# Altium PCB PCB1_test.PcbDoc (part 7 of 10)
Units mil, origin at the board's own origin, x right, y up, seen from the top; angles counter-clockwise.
Board outline 6690 x 6690 mil, 6 copper layers (Layer 1 - Top Layer, Layer 2 - GND, Layer 3 - PWR, Layer 4 - Signal, Layer 5 - GND, Layer 6 - Bottom Layer), stack 80.244 mil thick; 821 components, 458 nets, 3752 pads, 1525 vias.
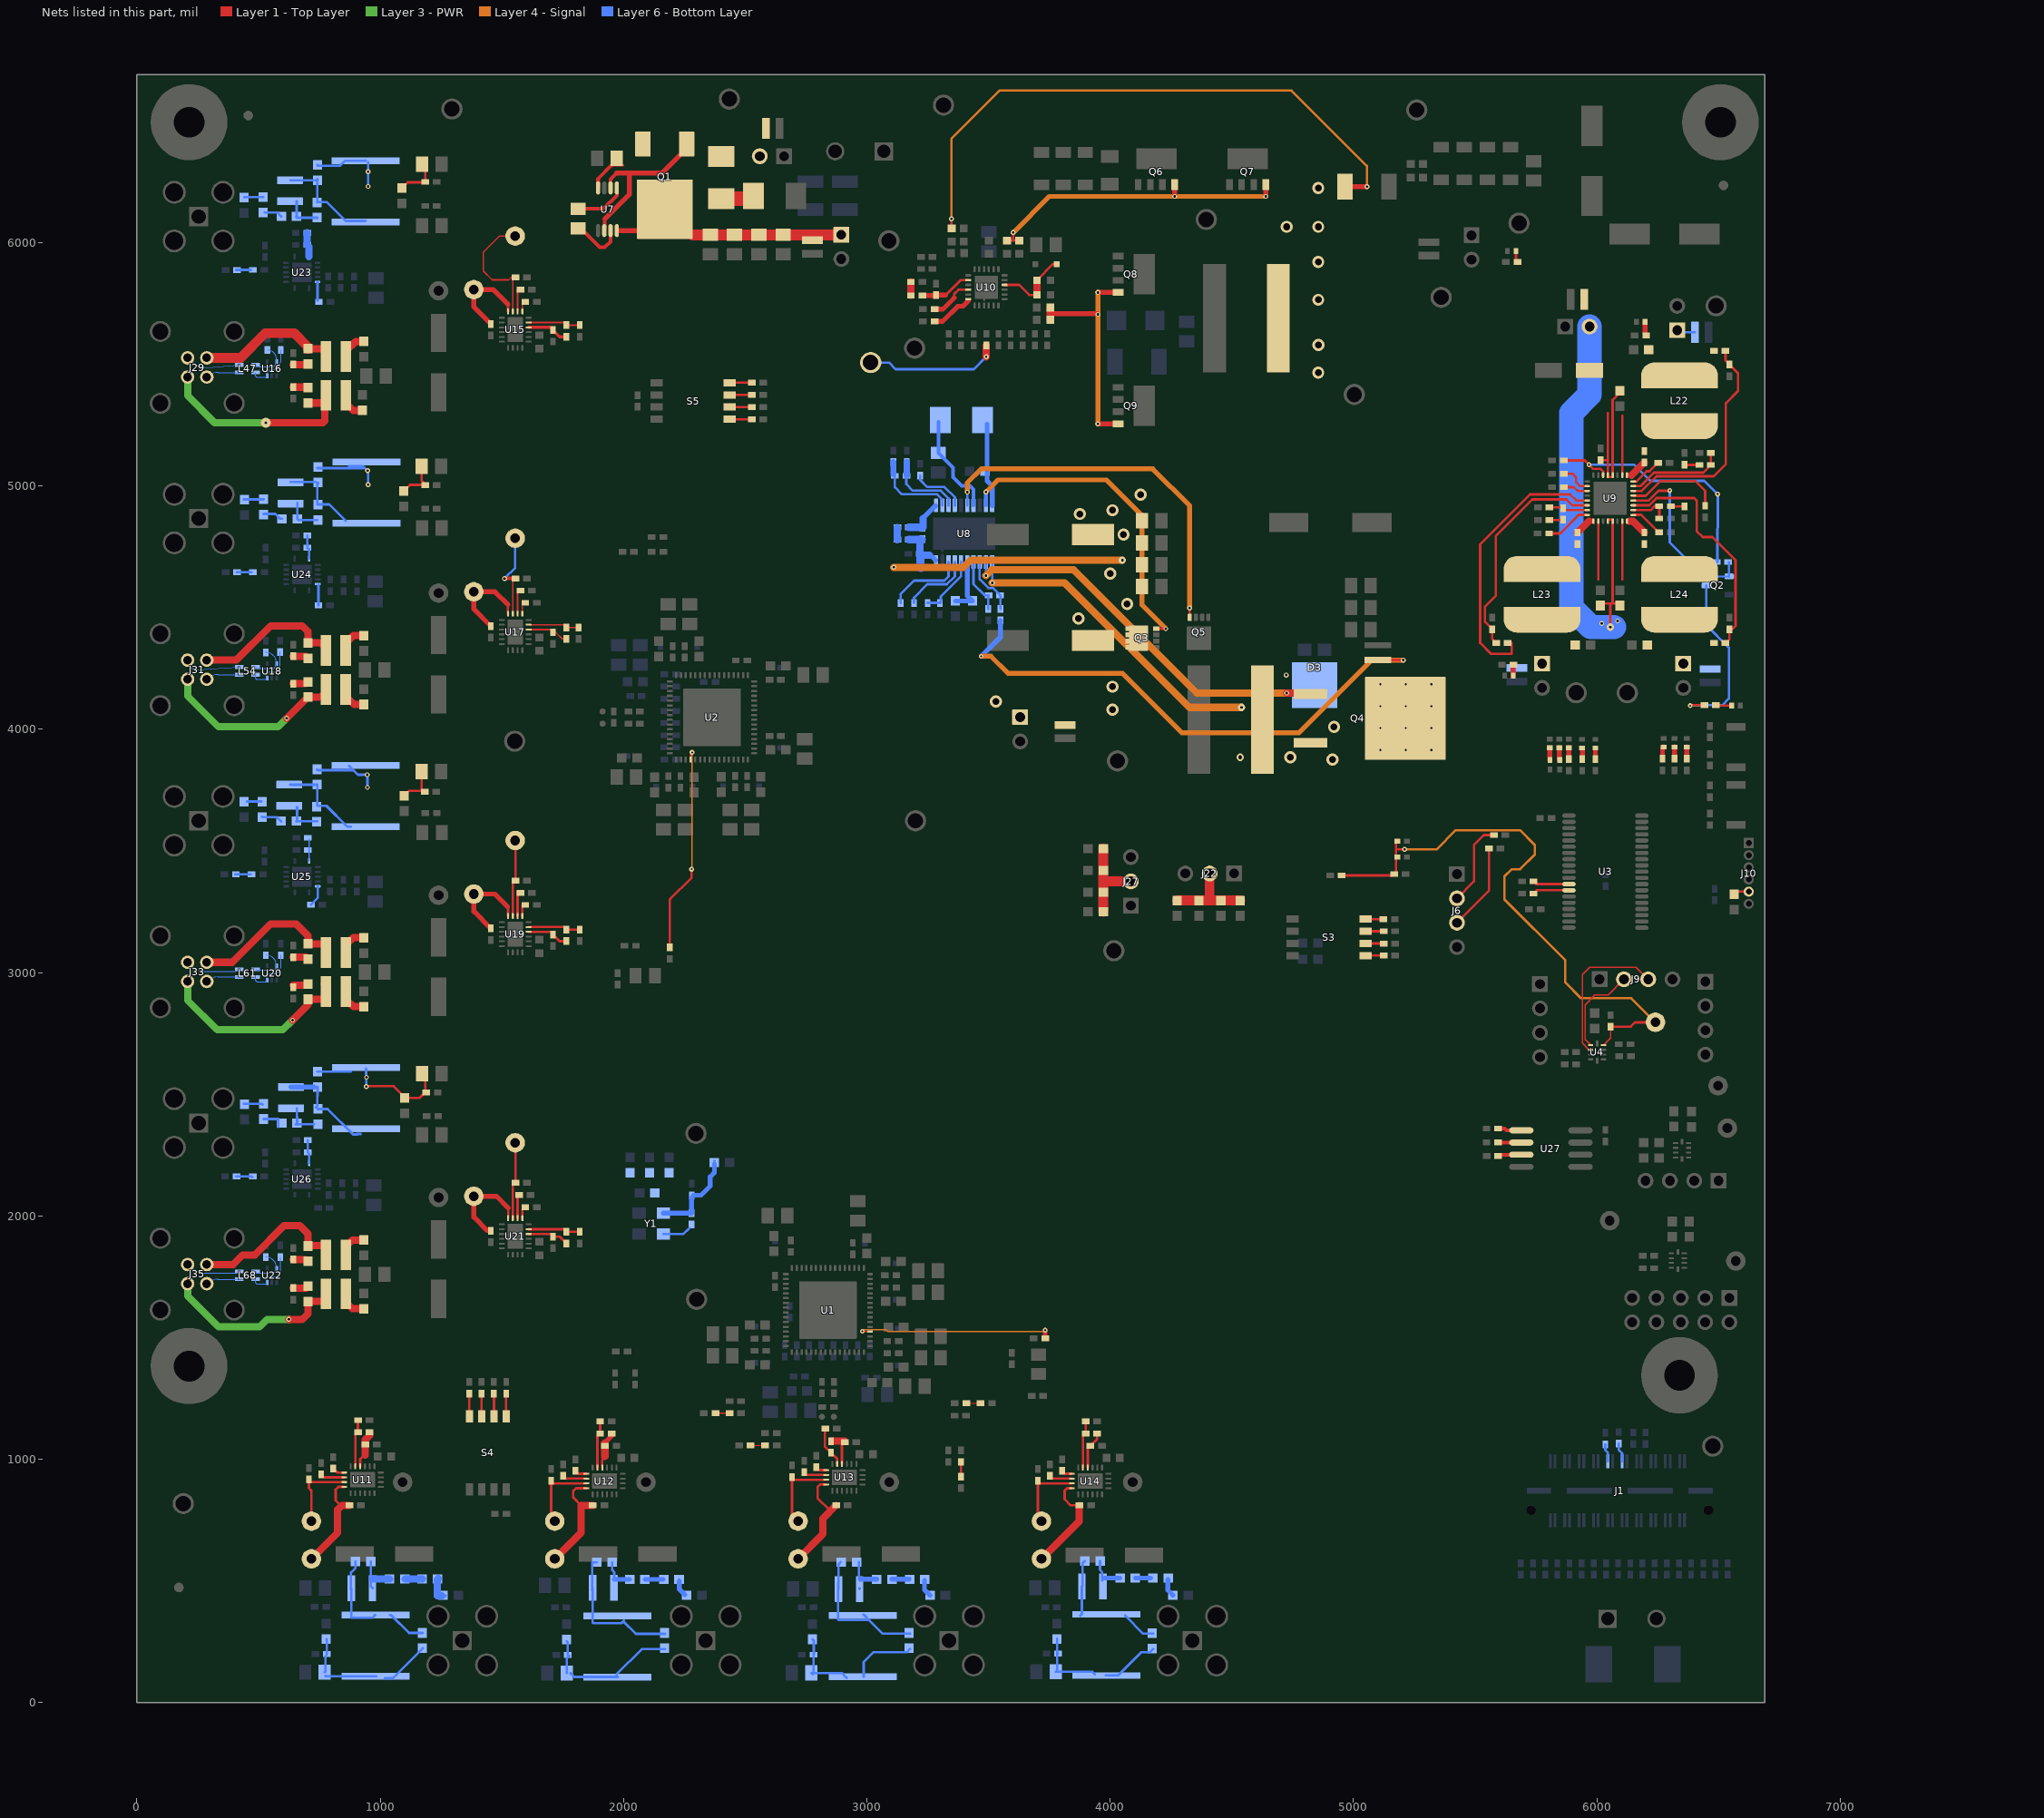
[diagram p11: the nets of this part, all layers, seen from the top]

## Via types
v1: diameter 20, hole 10, Layer 1 - Top Layer to Layer 6 - Bottom Layer, tented both sides, 491 vias
v2: diameter 20, hole 10, Layer 1 - Top Layer to Layer 6 - Bottom Layer, 310 vias
v3: diameter 19.68, hole 7.87, Layer 1 - Top Layer to Layer 6 - Bottom Layer, 274 vias
v4: diameter 19.68, hole 7.87, Layer 1 - Top Layer to Layer 6 - Bottom Layer, tented both sides, 217 vias
v5: diameter 50, hole 28, Layer 1 - Top Layer to Layer 6 - Bottom Layer, 101 vias
v6: diameter 30, hole 15, Layer 1 - Top Layer to Layer 6 - Bottom Layer, 73 vias
v7: diameter 22, hole 10, Layer 1 - Top Layer to Layer 6 - Bottom Layer, 36 vias
v8: diameter 30, hole 10, Layer 1 - Top Layer to Layer 6 - Bottom Layer, 14 vias
v9: diameter 19.68, hole 7.87, Layer 1 - Top Layer to Layer 6 - Bottom Layer, tented bottom, 4 vias
v10: diameter 30, hole 10, Layer 1 - Top Layer to Layer 6 - Bottom Layer, tented both sides, 2 vias
v11: diameter 40, hole 10, Layer 1 - Top Layer to Layer 6 - Bottom Layer, 1 vias
v12: diameter 23.62, hole 7.87, Layer 1 - Top Layer to Layer 6 - Bottom Layer, tented both sides, 1 vias
v13: diameter 23.62, hole 7.87, Layer 1 - Top Layer to Layer 6 - Bottom Layer, 1 vias

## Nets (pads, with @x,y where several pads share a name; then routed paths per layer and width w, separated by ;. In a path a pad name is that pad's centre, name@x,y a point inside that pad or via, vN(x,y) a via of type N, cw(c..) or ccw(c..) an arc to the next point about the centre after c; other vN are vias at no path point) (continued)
NetC132_1: C132.1 D1.1 J12.2 Q1.3 R173.2 U7.4 | length 197.8
  Layer 1 - Top Layer w10: C132.1@1951.2,6317.62 1997.89,6317.62
  Layer 1 - Top Layer w15: U7.4@1895.65,6224.71 1895.65,6262.07 C132.1@1951.2,6317.62 ; Q1.3@2070.76,6374.7 Q1.3@2095.67,6399.61
NetC133_1: C133.1 C134.1 C135.1 C136.1 J13.1 Q1.4 R172.1 U7.8 | length 689.6
  Layer 1 - Top Layer w10: Q1.4@2055.8,6049.51 Q1.4@2056.22,6049.92 ; Q1.4@2067.37,6089.94 Q1.4@2068.5,6091.06
  Layer 1 - Top Layer w20: U7.8@1978.82,6049.51 Q1.4@2055.8,6049.51
  Layer 1 - Top Layer w45: 2284.65,6032.05 C134.1@2357.5,6032.05 C135.1@2456.02,6032.05 C133.1@2656.02,6032.05 2770.71,6032.18 2775.97,6032.19 2783.97,6032.2 J13.1@2895.12,6032.32
NetC137_1: C137.1 U7.7 | length 197
  Layer 1 - Top Layer w15: C137.1@1832,6051.06 1902.38,5980.67 1923.53,5980.67 1946.56,6003.7 U7.7@1946.56,6047.43
NetC137_2: C137.2 U7.1 | length 217.8
  Layer 1 - Top Layer w15: C137.2@1808.17,6138.95 1917.46,6138.95 1972.42,6193.91 U7.1@1972.42,6224.71
NetC142_1: C142.1 C143.1 C144.1 C145.1 C146.1 C147.1 J16.1 Q3.5 Q3.6 Q3.7 Q3.8 Q3.9 R77.2 R187.1 | length 1010.6
  Layer 4 - Signal w30: v4(3110.86,4665.86) 3397.05,4665.86 3426.19,4695 v8(4050,4695)
  Layer 6 - Bottom Layer w20: v4(3110.86,4665.86) R77.2@3170.22,4665.86
  other v5: 4010,4080 3530,4115 4010,4175 3870,4455 4070,4515 4000,4640 4055,4800 3875,4885 4010,4900 4125,4965
NetC148_1: C148.1 R75.1 U8.5 | length 239.1
  Layer 6 - Bottom Layer w20: C148.1@3363.84,4527.35 R75.1@3433.84,4527.35 3412.64,4548.56 U8.5@3412.64,4687.72
NetC149_1: C149.1 R74.1 U8.3 | length 237.4
  Layer 6 - Bottom Layer w10: U8.3@3463.82,4687.72 3463.82,4615.88 3498.84,4580.86 3517.46,4580.86 C149.1@3547.46,4550.86 ; R74.1@3548.84,4494.48 C149.1@3548.84,4549.48
NetC149_2: C149.2 R73.1 U8.4 | length 227.1
  Layer 6 - Bottom Layer w10: U8.4@3438.23,4687.72 3438.23,4596.47 3483.84,4550.86 C149.2@3500.22,4550.86 ; R73.1@3498.84,4494.48 C149.2@3498.84,4549.48
NetC150_1: C150.1 U8.7 | length 284.5
  Layer 6 - Bottom Layer w10: C150.1@3193.84,4519.48 3193.84,4540.86 3248.84,4595.86 3328.84,4595.86 3361.46,4628.47 U8.7@3361.46,4687.72
NetC151_1: C151.1 U8.14 | length 223.1
  Layer 6 - Bottom Layer w10: C151.1@3218.84,5043.06 3218.84,5025.86 3248.84,4995.86 3318.84,4995.86 3361.46,4953.24 U8.14@3361.46,4920
NetC152_1: C152.1 D4.2 U8.17 | length 423.2
  Layer 6 - Bottom Layer w15: D4.2@3293.84,5262.87 C152.1@3293.84,5135.31 3353.84,5075.31 3353.84,5035.86 3388.84,5000.86 3423.84,5000.86 3438.23,4986.47 U8.17@3438.23,4920
NetC153_1: C153.1 C154.1 R77.1 R82.2 U8.10 | length 284.6
  Layer 6 - Bottom Layer w20: 3257.4,4720 U8.10@3283,4694
  Layer 6 - Bottom Layer w30: C154.1@3172.46,4779.66 C153.1@3227.46,4779.66 ; R77.1@3217.46,4665.86 R82.2@3217.46,4720.86 C153.1@3217.46,4768.54 ; R77.1@3221.09,4660.86 3221.09,4715.86 3256.54,4715.86
NetC153_2: C153.2 R84.1 U8.11 | length 170.2
  Layer 6 - Bottom Layer w20: 3227.86,4863.86 U8.11@3282,4918
  Layer 6 - Bottom Layer w30: R84.1@3172.79,4829.98 3230.54,4829.98 3230.54,4865.86
NetC154_2: C154.2 R84.2 | length 50
  Layer 6 - Bottom Layer w30: C154.2@3125.22,4779.66 R84.2@3125.22,4829.66
NetC155_1: C155.1 U9.25 | length 86.5
  Layer 1 - Top Layer w20: 6130,5045 6143.11,5044.49
  Layer 1 - Top Layer w30: 6143.11,5044.49 C155.1@6195,5096.38
NetC155_2: C155.2 L22.1 U9.26 | length 244.7
  Layer 1 - Top Layer w10: U9.26@6104.21,5044.49 6104.21,5289.21
NetC156_1: C156.1 J18.1 L22.2 R85.2 R201.1 | length 76.3
  Layer 6 - Bottom Layer w10: J18.1@6330,5640 6338,5632 R201.1@6403,5632
NetC157_2: C157.2 R86.2 | length 59.8
  Layer 1 - Top Layer w10: C157.2@6361.38,5086.38 R86.2@6421.15,5086.38
NetC158_1: C158.1 C_PVIN1.1 C_PVIN2.1 C_PVIN3.1 C_VIN1.1 J17.2 R200.2 U9.12 U9.13 U9.28 U9.29 | length 2594.1
  Layer 1 - Top Layer w10: C_PVIN2.1@6015,4516.38 6055,4516.38 ; C_VIN1.1@6015,5106.38 6043.78,5106.38 ; U9.12@6045,4862 U9.13@6064.68,4862 ; U9.29@6045,5037 U9.29@6045.16,5037 ; U9.29@6045.16,5036.74 U9.29@6045.16,5037 ; 6045.16,5299.84 U9.29@6045.16,5044.49 U9.29@6045.16,5037 ; v10(6055,4420) 6055,4516.38 ; 6064.84,4516.54 U9.13@6064.84,4855.51 ; U9.28@6064.84,5044.49 6064.84,5353.46 6095,5383.62 C_PVIN1.1@6095,5385 ; U9.28@6065,5037 U9.29@6045.16,5037 ; C_PVIN3.1@6095,4516.38 6055,4516.38
  Layer 6 - Bottom Layer w100: J17.2@5970,5655 5970,5375 5895,5300 5895,4500 5975,4420 v10(6055,4420) 6070,4420
  other v1: 6020,4435 6085,4445
NetC159_2: C159.2 R86.1 U9.23 | length 404.8
  Layer 1 - Top Layer w10: U9.23@6149.49,4999.21 6179.21,4999.21 6235,5055 6437.02,5055 R86.1@6468.4,5086.38 C159.2@6468.4,5136.15
NetC160_1: C160.1 U9.9 | length 78.9
  Layer 1 - Top Layer w20: 5966.89,4855.51 5979.51,4855.51
  Layer 1 - Top Layer w30: C160.1@5920,4808.62 5966.89,4855.51
NetC160_2: C160.2 L23.1 U9.10 | length 239.7
  Layer 1 - Top Layer w10: 6005.79,4615.79 U9.10@6005.79,4855.51
NetC161_1: C161.1 J19.1 L23.2 R91.2 R214.1 U9.5 | length 1150.7
  Layer 1 - Top Layer w10: R91.2@5633.62,4355 5650,4355 5650,4310 5565,4310 5520,4355 5520,4760 5725,4965 5890,4965 5914.84,4940.16 U9.5@5960.51,4940.16
NetC162_2: C162.2 R94.2 | length 55
  Layer 1 - Top Layer w10: C162.2@5804.84,4860 R94.2@5859.84,4860
NetC163_2: C163.2 R94.1 U9.7 | length 144.6
  Layer 1 - Top Layer w10: C163.2@5804.64,4912.04 R94.1@5857.8,4912.04 ; R94.1@5869.05,4900.79 U9.7@5960.51,4900.79
NetC164_1: C164.1 U9.16 | length 81.4
  Layer 1 - Top Layer w30: 6133,4855 6148.11,4855.51 C164.1@6195,4808.62
NetC164_2: C164.2 L24.1 U9.15 | length 239.7
  Layer 1 - Top Layer w10: 6104.21,4615.79 U9.15@6104.21,4855.51
NetC165_1: C165.1 J20.1 L24.2 R97.2 R215.1
NetC166_2: C166.2 R98.2 | length 55
  Layer 1 - Top Layer w10: R98.2@6305,4915.28 C166.2@6360,4915.28
NetC167_1: C167.1 R89.2 U9.30 | length 1053.5
  Layer 1 - Top Layer w10: C167.1@5863.62,5105 5950,5105 v4(5967.5,5087.5) 5985,5070 6015,5070 6025.47,5059.53 U9.30@6025.47,5044.49
  Layer 6 - Bottom Layer w10: v4(5967.5,5087.5) 6152.5,5087.5 6218.83,5021.17 6440.84,5021.17 6497.14,4964.88 R89.2@6495.51,4687.57
  other v4: 6496,4966.58
NetC168_1: C168.1 U9.24 | length 133.4
  Layer 1 - Top Layer w10: U9.24@6149.49,5018.9 6163.9,5018.9 6205,5060 6216.38,5060 C168.1@6251.38,5095
NetC169_1: C169.1 U9.8 | length 188.4
  Layer 1 - Top Layer w10: C169.1@5803.62,4805 5849.72,4805 5925.82,4881.1 U9.8@5960.51,4881.1
NetC170_1: C170.1 U9.17 | length 136.3
  Layer 1 - Top Layer w10: U9.17@6149.49,4881.1 6181.34,4881.1 6252.44,4810 C170.1@6256.38,4810
NetC171_2: C171.2 R98.1 U9.18 | length 163.5
  Layer 1 - Top Layer w10: U9.18@6149.49,4900.79 6220.79,4900.79 6236.65,4916.65 R98.1@6256.38,4916.65 C171.2@6256.38,4866.65
NetC180_1: C180.1 C181.2 D9.2 U10.10 | length 318.1
  Layer 1 - Top Layer w10: U10.10@3566.18,5826.22 3626.54,5826.22 3667.76,5785 C181.2@3698.38,5785 ; C180.1@3698.38,5845 3764.76,5911.38 D9.2@3779.69,5911.38
  Layer 1 - Top Layer w30: C181.2@3698.38,5785 C180.1@3698.38,5845
NetC192_1: C192.1 U10.22 | length 181
  Layer 1 - Top Layer w10: 3359,5773 3359,5789 3376.54,5806.54 U10.22@3416.57,5806.54
  Layer 1 - Top Layer w20: C192.1@3278.19,5726.38 3312.38,5726.38 3359,5773
NetC193_1: C193.1 U10.24 | length 172.8
  Layer 1 - Top Layer w20: C193.1@3278.19,5676.38 3311.38,5676.38 3374,5739 3396,5739 3416.57,5759.57
NetC194_2: C194.2 R123.2 U10.20 | length 212.5
  Layer 1 - Top Layer w10: 3324.41,5784.41 3385.91,5845.91 U10.20@3416.57,5845.91
  Layer 1 - Top Layer w20: R123.2@3228.19,5783.03 C194.2@3283.19,5783.03 ; C194.2@3284.57,5784.41 3324.41,5784.41
NetC195_1: C195.1 R123.1 | length 55
  Layer 1 - Top Layer w30: R123.1@3180.94,5783.03 C195.1@3180.94,5838.03
NetC196_1: C196.1 C197.1 L26.1 L79.2 R134.2 | length 543.3
  Layer 6 - Bottom Layer w10: C197.1@772.27,125.13 775,127.86 C196.1@775,190 ; C197.1@775,110 776.89,108.11 L79.2@984.13,108.11 ; L26.1@780,260 780.9,259.1 C196.1@780.9,199.13 ; L79.2@1020,100 1051.5,100 R134.2@1175,223.5
NetC200_1: C200.1 C201.1 L27.1 L80.2 R135.2 | length 580.1
  Layer 6 - Bottom Layer w10: C201.1@1766.93,121.41 1766.93,181.41 C200.1@1776.93,191.41 ; L27.1@1766.93,251.41 1770.56,247.79 C200.1@1770.56,196.41 ; C201.1@1781.93,121.41 1797.92,105.43 L80.2@1976.93,105.43 ; L80.2@1971.93,111.41 1971.93,116.41 2075.44,219.91 R135.2@2171.93,219.91
NetC206_1: C206.1 R132.2 | length 55.6
  Layer 1 - Top Layer w5: R132.2@2383.41,1190 C206.1@2436.38,1190
  Layer 1 - Top Layer w10: R132.2@2381,1189 cw(c2383.41,1186.59) R132.2@2383.41,1190
NetC207_1: C207.1 R133.2 | length 66
  Layer 1 - Top Layer w3.94: R133.2@2522.62,1057 C207.1@2582.38,1057
  Layer 1 - Top Layer w10: R133.2@2518,1053 2522,1057 R133.2@2522.62,1057
NetC214_1: C214.1 U11.18 | length 100
  Layer 1 - Top Layer w5: C214.1@757.56,937.24 C214.1@769.09,925.71
  Layer 1 - Top Layer w10: C214.1@769.09,925.71 U11.18@852.75,925.71
NetC215_1: C215.1 U12.18 | length 83.7
  Layer 1 - Top Layer w10: C215.1@1764.09,920.71 U12.18@1847.75,920.71
NetC216_1: C216.1 C217.1 L34.1 L81.2 R154.2 | length 572.5
  Layer 6 - Bottom Layer w10: C217.1@2771.93,121.92 C217.1@2780.56,121.92 ; C217.1@2776.93,116.92 2780.56,120.54 C217.1@2780.56,121.92 ; L34.1@2776.93,260.43 2781.93,255.42 C216.1@2781.93,196.92 ; C216.1@2780.56,196.92 C217.1@2780.56,121.92 ; L81.2@2916.93,101.92 2896.93,121.92 C217.1@2780.56,121.92 ; L81.2@2986.93,106.92 2986.93,166.92 3026.93,206.92 3163.43,206.92 R154.2@3176.93,220.43
NetC220_1: C220.1 C221.1 L35.1 L82.2 R155.2 | length 535.6
  Layer 6 - Bottom Layer w10: C221.1@3776.93,126.92 3926.93,126.92 L82.2@3936.93,116.92 ; C221.1@3781.93,131.92 3781.93,198.3 C220.1@3785.56,201.92 ; C220.1@3781.93,201.92 L35.1@3781.93,261.92 ; L82.2@3981.93,111.92 4031.93,111.92 4126.93,206.92 4163.43,206.92 R155.2@4176.93,220.43
NetC226_1: C226.1 R152.2 | length 68.4
  Layer 1 - Top Layer w10: C226.1@3386.56,989.24 3386.56,922.07 ccw(c3388.07,922.07) R152.2@3387,921
NetC227_1: C227.1 R153.2 | length 56.6
  Layer 1 - Top Layer w3.94: C227.1@3408.62,1230 R153.2@3462.59,1230
  Layer 1 - Top Layer w10: R153.2@3462.59,1230 ccw(c3462.59,1233.41) R153.2@3465,1231
NetC234_1: C234.1 U13.18 | length 78.7
  Layer 1 - Top Layer w10: C234.1@2754.09,935.71 U13.18@2832.75,935.71
NetC235_1: C235.1 U14.18 | length 78.7
  Layer 1 - Top Layer w10: C235.1@3764.09,920.71 U14.18@3842.75,920.71
NetC236_1: C236.1 C237.1 L42.1 L83.2 R185.2 | length 495.5
  Layer 1 - Top Layer w10: L42.1@1089,6224 1113,6248 1180.5,6248 1185,6252.5 1185,6309.5 C237.1@1172,6322.5
  Layer 6 - Bottom Layer w10: R185.2@742.28,6320.02 R185.2@746.28,6316.02 ; R185.2@744,6316 835,6316 855.02,6336.02 L83.2@940.28,6336.02 940.28,6336.72 L83.2@940,6337 ; v2@950,6228 v2(950,6231) v2@950,6289 ; v2(950,6291) L83.2@950,6331
NetC241_1: C241.1 L47.3 U16.3 | length 209
  Layer 6 - Bottom Layer w3.94: L47.3@488.46,5466.25 488.46,5452.54 ccw(c494,5452.54) 494,5447 529.84,5447 ccw(c529.84,5452.47) U16.3@535.32,5452.47 535.31,5466.31 cw(c544,5466.31) 544,5475 548.59,5475 ccw(c548.59,5520) 593.59,5520 593.59,5556.6 ccw(c591.81,5556.6) C241.1@591.81,5558.38
NetC244_1: C244.1 L47.2 U16.5 | length 169
  Layer 6 - Bottom Layer w3.94: L47.2@488.46,5497.75 ccw(c507.17,5516.45) 507.17,5490 553.16,5490 ccw(c553.16,5511.53) U16.5@574.69,5511.53 574.69,5520.5 ccw(c536.81,5520.5) C244.1@536.81,5558.38
NetC246_1: C246.1 U15.18 | length 90.4
  Layer 1 - Top Layer w6: U15.18@1564.84,5716.8 C246.1@1564.84,5807.16
NetC247_1: C247.1 J29.3 L45.1 | length 856.7
  Layer 1 - Top Layer w30: v11(530,5260) 765,5260 ; C247.1@703,5340.88 L45.1@772.5,5340.88 ; 770,5265 772.92,5267.92 L45.1@772.92,5372.38
  Layer 3 - PWR w30: J29.3@208.94,5447.63 208.94,5371.06 320,5260 v11(530,5260)
NetC247_2: C247.2 R182.2 | length 57.9
  Layer 1 - Top Layer w30: R182.2@643,5406 C247.2@700.87,5406
NetC248_1: C248.1 J29.1 L46.1 | length 588.3
  Layer 1 - Top Layer w10: L46.1@769.5,5563.87 772.92,5560.46 L46.1@772.92,5532.38
  Layer 1 - Top Layer w30: C248.1@703,5563.87 L46.1@769.5,5563.87
  Layer 1 - Top Layer w40: J29.1@287.68,5526.37 426.37,5526.37 527.87,5627.87 647.49,5627.87 703,5572.37 C248.1@703,5563.87
NetC248_2: C248.2 R183.2 | length 57.9
  Layer 1 - Top Layer w30: R183.2@643,5498.76 C248.2@700.87,5498.76
NetC249_1: C249.1 R184.2 | length 61.4
  Layer 6 - Bottom Layer w10: R184.2@407.62,5888 C249.1@469,5888
NetC251_1: C251.1 C252.1 L49.1 L84.2 R199.2 | length 512.2
  Layer 1 - Top Layer w10: L49.1@1097,4979 1122.5,5004.5 C251.1@1183,5004.5 ; C252.1@1171,5080.5 1171,5021.5 C251.1@1189,5003.5
  Layer 6 - Bottom Layer w10: R199.2@742,5073.47 927.3,5073.47 ccw(c927.3,5095.67) 935.11,5074.89 ; 872,5081 929,5081 935.11,5074.89 ; v2@948,5062 935.11,5074.89 ; v2(951,5005) v2@951,5059
  other v2: 949,5063
NetC256_1: C256.1 L54.3 U18.3 | length 210.3
  Layer 6 - Bottom Layer w3.94: L54.3@488.46,4224.25 488.46,4210.54 ccw(c494,4210.54) 494,4205 529.84,4205 ccw(c529.84,4210.47) U18.3@535.32,4210.47 535.31,4224.31 cw(c546,4224.31) 546,4235 559.84,4235 ccw(c559.84,4264.16) 589,4264.16 C256.1@589,4317.38
NetC259_1: C259.1 L54.2 U18.5 | length 171.3
  Layer 6 - Bottom Layer w3.94: L54.2@488.46,4255.75 ccw(c502.34,4269.62) 502.34,4250 555.16,4250 ccw(c555.16,4269.53) U18.5@574.69,4269.53 574.69,4271.69 ccw(c530,4271.69) C259.1@530,4316.38
NetC261_1: C261.1 U17.18 | length 83.7
  Layer 1 - Top Layer w6: U17.18@1564.84,4474.8 C261.1@1564.84,4558.46
NetC262_1: C262.1 J31.3 L52.1 | length 755.5
  Layer 1 - Top Layer w10: 741.3,4132.09 L52.1@772.84,4163.62
  Layer 1 - Top Layer w30: v2(615.83,4045) C262.1@702.91,4132.09 741.3,4132.09 747.91,4132.09
  Layer 3 - PWR w30: J31.3@208.94,4205.63 208.94,4136.73 335.67,4010 580.83,4010 v2(615.83,4045)
NetC262_2: C262.2 R195.2 | length 52.2
  Layer 1 - Top Layer w30: R195.2@642.91,4187.24 C262.2@695.08,4187.24
NetC263_1: C263.1 J31.1 L53.1 | length 621.5
  Layer 1 - Top Layer w10: 741.38,4355.08 L53.1@772.84,4323.62
  Layer 1 - Top Layer w30: J31.1@287.68,4284.37 409.37,4284.37 550,4425 680,4425 702.91,4402.09 C263.1@702.91,4355.08 741.38,4355.08 749.92,4355.08
NetC263_2: C263.2 R196.2 | length 52.1
  Layer 1 - Top Layer w30: R196.2@642.91,4300 C263.2@695,4300
NetC264_1: C264.1 R198.2 | length 61.4
  Layer 6 - Bottom Layer w10: R198.2@409.62,4645.97 R198.2@412.62,4645.97 C264.1@471,4645.97
NetC266_1: C266.1 C267.1 L56.1 L85.2 R213.2 | length 466.2
  Layer 1 - Top Layer w10: L56.1@1098.38,3727.12 1118.88,3747.62 C266.1@1177.38,3747.62 ; C267.1@1170.38,3826.62 1170.38,3754.62 C266.1@1177.38,3747.62 ; C266.1@1179.38,3747.62 C266.1@1177.38,3747.62 ; C266.1@1180.38,3744.62 C266.1@1177.38,3747.62
  Layer 6 - Bottom Layer w10: R213.2@739.5,3835 742.53,3831.97 890.03,3831.97 ; L85.2@873,3849 890.03,3831.97 ; v2@946,3810 948,3808 v2(948,3761) ; v2(947,3813) 909,3813 890.03,3831.97
NetC271_1: C271.1 L61.3 U20.3 | length 209.6
  Layer 6 - Bottom Layer w3.94: L61.3@488.46,2982.25 488.46,2968.54 ccw(c494,2968.54) 494,2963 529.84,2963 ccw(c529.84,2968.47) U20.3@535.32,2968.47 535.32,2985.32 cw(c545,2985.32) 545,2995 561.84,2995 ccw(c561.84,3025.56) 592.4,3025.56 C271.1@592.4,3071.38
NetC274_1: C274.1 L61.2 U20.5 | length 166.1
  Layer 6 - Bottom Layer w3.94: L61.2@488.46,3013.75 ccw(c497.51,3022.8) 497.51,3010 557.16,3010 ccw(c557.16,3027.53) U20.5@574.69,3027.53 ccw(c530.84,3027.53) C274.1@530.84,3071.38
NetC276_1: C276.1 U19.18 | length 102
  Layer 1 - Top Layer w10: U19.18@1564.84,3232.8 C276.1@1564.84,3334.84
NetC277_1: C277.1 J33.3 L59.1 | length 819
  Layer 1 - Top Layer w30: v2(640,2805) 703,2868 C277.1@703,2890.5 770.5,2890.5 772.92,2892.92 772.92,2952.08 L59.1@771.5,2953.5
  Layer 3 - PWR w30: J33.3@208.94,2963.63 208.94,2886.06 330,2765 600,2765 v2(640,2805)
NetC277_2: C277.2 R210.2 | length 69.7
  Layer 1 - Top Layer w10: R210.2@643,2940.62 R210.2@643,2948 ; C277.2@697.5,2948 C277.2@703,2953.5
  Layer 1 - Top Layer w30: R210.2@643,2948 C277.2@697.5,2948
NetC278_1: C278.1 J33.1 L60.1 | length 639.6
  Layer 1 - Top Layer w30: J33.1@287.68,3042.37 392.37,3042.37 550,3200 655,3200 703,3152 C278.1@703,3118.5 771.5,3118.5 772.92,3117.08 L60.1@772.92,3082
NetC278_2: C278.2 R211.2 | length 52.1
  Layer 1 - Top Layer w30: R211.2@643,3063.38 C278.2@695.13,3063.38
NetC279_1: C279.1 R212.2 | length 61.4
  Layer 6 - Bottom Layer w10: R212.2@405.12,3404 R212.2@407.12,3404 C279.1@466.5,3404
NetC281_1: C281.1 C282.1 L63.1 L86.2 R227.2 | length 568.9
  Layer 1 - Top Layer w10: v2@944,2533 1055.61,2533 L63.1@1103,2485.61 ; L63.1@1104,2484.61 L63.1@1103,2485.61 ; C282.1@1173,2585 1186,2572 C281.1@1186,2514.61 ; C281.1@1189.38,2508 1185.39,2508 1163,2485.61 L63.1@1103,2485.61
  Layer 6 - Bottom Layer w10: R227.2@743,2593.5 879.5,2593.5 ; v2@938,2533 v2@941,2530 ; L86.2@941,2605 942,2604 942,2583 943,2582 v2(943,2532) ; v2@942,2531 v2@944,2529
  other v2: 944,2570
NetC286_1: C286.1 L68.3 U22.3 | length 215.8
  Layer 6 - Bottom Layer w3.94: L68.3@488.46,1740.25 488.46,1726.54 ccw(c494,1726.54) 494,1721 529.84,1721 ccw(c529.84,1726.47) U22.3@535.32,1726.47 535.32,1740.32 cw(c545,1740.32) 545,1750 575,1750 ccw(c575,1765) 590,1765 C286.1@590,1831.38
NetC289_1: C289.1 L68.2 U22.5 | length 173.1
  Layer 6 - Bottom Layer w3.94: L68.2@488.46,1771.75 ccw(c495.21,1771.75) 495.21,1765 554.16,1765 ccw(c554.16,1785.53) U22.5@574.68,1785.53 574.68,1786.69 ccw(c530,1786.69) C289.1@530,1831.38
NetC291_1: C291.1 U21.18 | length 88.7
  Layer 1 - Top Layer w10: U21.18@1564.84,1990.8 C291.1@1564.84,2079.46
NetC292_1: C292.1 J35.3 L66.1 | length 769.5
  Layer 1 - Top Layer w30: v2(625,1575) 680,1575 703,1598 C292.1@703,1648.5 769.35,1648.5 772.92,1652.08 L66.1@772.92,1680
  Layer 3 - PWR w30: J35.3@208.94,1721.63 208.94,1671.06 336,1544 504,1544 535,1575 v2(625,1575)
NetC292_2: C292.2 R223.2 | length 63.3
  Layer 1 - Top Layer w30: R223.2@643,1703.62 695.13,1703.62 C292.2@703,1711.5
NetC293_1: C293.1 J35.1 L67.1 | length 652
  Layer 1 - Top Layer w30: J35.1@287.68,1800.37 395.37,1800.37 435,1840 485,1840 605,1960 670,1960 703,1927 C293.1@703,1876.5 ; C293.1@704.43,1877.92 772.92,1877.92 L67.1@772.92,1840
NetC293_2: C293.2 R224.2 | length 63.3
  Layer 1 - Top Layer w30: R224.2@643,1821.38 695.13,1821.38 C293.2@703,1813.5
NetC294_1: C294.1 R226.2 | length 67.2
  Layer 6 - Bottom Layer w10: R226.2@408,2162 R226.2@409.62,2162 471,2162 C294.1@474,2159
NetC313_1: C313.1 L78.1 R31.2 Y1.4 | length 357.9
  Layer 6 - Bottom Layer w10: C313.1@2277.92,2075.97 C313.1@2280.09,2073.8 ; L78.1@2373.21,2226.43 L78.1@2373.62,2226.02
  Layer 6 - Bottom Layer w20: Y1.4@2164.1,2012.02 R31.2@2272.78,2012.02 ; R31.2@2280.09,2011.88 C313.1@2280.09,2073.8 ; C313.1@2286.5,2084.99 2318.69,2084.99 2356.03,2122.32 2356.03,2160.41 2373.63,2178 L78.1@2373.63,2213.74
NetCbst1_2: Cbst1.2 D4.1 U8.20 | length 341.6
  Layer 6 - Bottom Layer w20: D4.1@3493.84,5252.87 3493.84,5020.86 3515,4999.7 U8.20@3515,4920
NetD1_2: D1.2 D2.2 | length 121
  Layer 1 - Top Layer w60: D1.2@2401.02,6180.04 D2.2@2522.01,6180.04
NetD3_3: D3.3 L21.1 Q4.3 U8.1 | length 1322.8
  Layer 4 - Signal w30: v2(3515,4602.02) 3812.98,4602.02 4325,4090 v8(4540,4090)
  Layer 6 - Bottom Layer w10: v2(3515,4602.02) U8.1@3515,4687.72
  other v2: 4724,4223
  other v5: 4913,3875 4740,3885 4920,4010
  other v6: 4535,3885
NetD5_2: D5.2 R88.1 | length 50.9
  Layer 1 - Top Layer w20: R88.1@6197.72,5623.91 D5.2@6197.72,5674.76
NetD6_2: D6.2 R96.2 | length 44.1
  Layer 1 - Top Layer w20: D6.2@5656.06,4220 R96.2@5656.06,4264.09
NetD7_1: D7.1 R102.2 | length 67.9
  Layer 1 - Top Layer w10: R102.2@6486.41,4098.12 6487.57,4096.96 D7.1@6553.85,4096.96
NetD10_2: D10.2 R121.1 | length 39.1
  Layer 1 - Top Layer w10: R121.1@5667.72,5925.91 D10.2@5667.72,5965
NetD11_1: D11.1 R248.1 | length 48.7
  Layer 1 - Top Layer w20: R248.1@6369.5,3878.62 D11.1@6369.5,3927.28
NetD12_1: D12.1 R249.1 | length 48.7
  Layer 1 - Top Layer w20: R249.1@6319.5,3878.62 D12.1@6319.5,3927.28
NetD13_2: D13.2 R250.1 | length 50.7
  Layer 1 - Top Layer w20: R250.1@6269.5,3878.62 6269.5,3922.28 D13.2@6274.5,3927.28
NetD15_2: D15.2 R51.1 | length 46.9
  Layer 1 - Top Layer w20: R51.1@5885,3877.24 D15.2@5885,3924.19
NetD16_1: D16.1 R58.1 | length 50
  Layer 1 - Top Layer w20: D16.1@5846,3923.91 5846,3875.31 R58.1@5847,3874.31
NetD17_1: D17.1 R59.1 | length 50
  Layer 1 - Top Layer w20: D17.1@5806,3923.91 5806,3875.31 R59.1@5807,3874.31
NetD18_2: D18.2 R60.1 | length 46.1
  Layer 1 - Top Layer w20: D18.2@5939,3922.91 5940,3921.91 R60.1@5940,3877.24
NetD19_2: D19.2 R61.1 | length 45.7
  Layer 1 - Top Layer w20: R61.1@5994,3877.24 D19.2@5994,3922.91
NetJ1_18: J1.18 R47.1 | length 73
  Layer 6 - Bottom Layer w10: R47.1@6035,1061.38 6035,1037.43 6044.86,1027.57 J1.18@6044.86,992.46
NetJ1_22: J1.22 R48.1 | length 78.3
  Layer 6 - Bottom Layer w10: R48.1@6090,1065 6090,1038.31 6103.92,1024.39 J1.22@6103.92,992.46
NetJ6_2: J6.2 R45.2 | length 346.9
  Layer 1 - Top Layer w10: J6.2@5425,3305 5495,3375 5495,3525 5535,3565 R45.2@5576.38,3565
NetJ6_3: J6.3 R46.2 | length 359.4
  Layer 1 - Top Layer w10: J6.3@5425,3205 5556.38,3336.38 R46.2@5556.38,3510
NetJ9_2: J9.2 U4.1 | length 378.7
  Layer 1 - Top Layer w5: U4.1@5974.41,2702.38 5950.98,2725.81 5950.98,2867.86 5990.98,2907.86 6045.98,2907.86 J9.2@6110.98,2972.86
NetJ9_3: J9.3 U4.2 | length 632.1
  Layer 1 - Top Layer w5: U4.2@5974.41,2682.7 5967.3,2682.7 5940,2710 5940,2991.87 5970.98,3022.86 6160.98,3022.86 J9.3@6210.98,2972.86
NetJ10_5: J10.5 R66.1 | length 63.7
  Layer 1 - Top Layer w10: R66.1@6565,3321.5 6576.32,3332.81 J10.5@6624.02,3332.81
NetJ22_2: J22.2 R128.2 R129.2 R130.2 R131.2 | length 364.5
  Layer 1 - Top Layer w40: R128.2@4275,3296.5 R129.2@4365,3296.5 R130.2@4455,3296.5 R131.2@4535,3296.5 ; 4408.74,3302.92 J22.2@4408.74,3407.39
NetJ27_2: J27.2 R168.2 R169.2 R170.2 R171.2 | length 372.5
  Layer 1 - Top Layer w40: R171.2@3971.5,3250 R170.2@3971.5,3330 R169.2@3971.5,3420 R168.2@3971.5,3510 ; 3972.5,3375 J27.2@4085,3375
NetJ29_2: J29.2 L47.1 | length 225.2
  Layer 6 - Bottom Layer w3.94: J29.2@208.94,5526.37 219.35,5515.96 ccw(c290.06,5586.67) 290.06,5486.67 L47.1@421.54,5497.75
NetJ29_4: J29.4 L47.4 | length 138.8
  Layer 6 - Bottom Layer w3.94: J29.4@287.68,5447.63 cw(c332.64,5402.67) 332.64,5466.25 L47.4@421.54,5466.25
NetJ31_2: J31.2 L54.1 | length 235.4
  Layer 6 - Bottom Layer w3.94: J31.2@208.94,4284.37 ccw(c248.31,4284.37) 248.31,4245 L54.1@421.54,4255.75
NetJ31_4: J31.4 L54.4 | length 138.8
  Layer 6 - Bottom Layer w3.94: J31.4@287.68,4205.63 cw(c332.63,4160.67) 332.63,4224.25 L54.4@421.54,4224.25
NetJ33_2: J33.2 L61.1 | length 226.1
  Layer 6 - Bottom Layer w3.94: J33.2@208.94,3042.37 217.02,3034.29 ccw(c287.73,3105) 287.73,3005 400.42,3005 ccw(c400.42,3034.87) L61.1@421.54,3013.75
NetJ33_4: J33.4 L61.4 | length 138.8
  Layer 6 - Bottom Layer w3.94: J33.4@287.68,2963.63 cw(c332.63,2918.68) 332.63,2982.25 L61.4@421.54,2982.25
NetJ35_2: J35.2 L68.1 | length 224.7
  Layer 6 - Bottom Layer w3.94: J35.2@208.94,1800.37 215.02,1794.29 ccw(c285.73,1865) 285.73,1765 405.24,1765 ccw(c405.24,1788.04) L68.1@421.54,1771.75
NetJ35_4: J35.4 L68.4 | length 138.8
  Layer 6 - Bottom Layer w3.94: J35.4@287.68,1721.63 cw(c332.64,1676.67) 332.64,1740.25 L68.4@421.54,1740.25
NetL25_2: L25.2 R117.1 R118.2 | length 2461.6
  Layer 1 - Top Layer w10: R118.2@3348.03,6058.94 v2(3348.03,6098.03)
  Layer 1 - Top Layer w20: R117.1@4964.45,6230 v2(5055,6230)
  Layer 4 - Signal w10: v2(3348.03,6098.03) 3348.03,6428.03 3545,6625 4745,6625 5055,6315 v2(5055,6230)
  other v5: 4855,5465 4856,5579 4855,5765 4855,5920 4725,6065 4855,6065 4855,6225
NetL28_1: L28.1 L30.2 R62.1 | length 183.5
  Layer 6 - Bottom Layer w10: R62.1@961.5,580 961.5,478.5 L28.1@970,470
  Layer 6 - Bottom Layer w30: L28.1@968.45,508.45 L30.2@1038.45,508.45
NetL28_2: L28.2 L79.1 R62.2 R134.1 | length 513
  Layer 6 - Bottom Layer w10: L28.2@880,465 880,535 898.5,553.5 R62.2@898.5,580 ; L28.2@881.69,470 881.69,348.31 968.31,348.31 L79.1@980,360 ; L79.1@1040,360 1045,360 1118.5,286.5 R134.1@1173,286.5 R134.1@1175,286.5
NetL29_1: L29.1 L31.2 R92.1 | length 137
  Layer 6 - Bottom Layer w10: R92.1@1953.43,576.41 1953.43,544.91 1961.93,536.41 L29.1@1961.93,506.41
  Layer 6 - Bottom Layer w20: L29.1@1961.93,506.41 L31.2@2025.44,506.41
NetL29_2: L29.2 L80.1 R92.2 R135.1 | length 603.6
  Layer 6 - Bottom Layer w10: L29.2@1871.93,461.41 1871.93,576.41 R92.2@1890.44,576.41 ; L29.2@1873.63,471.41 1873.63,328.1 1875.32,326.41 1991.93,326.41 1999.43,333.91 ; 2001.93,336.41 1999.43,333.91 ; R135.1@2171.93,282.91 2050.44,282.91 1999.43,333.91
NetL30_1: L30.1 L32.2 | length 70
  Layer 6 - Bottom Layer w30: L30.1@1103.45,508.45 L32.2@1172.44,508.45 L32.2@1173.45,508.45
NetL31_1: L31.1 L33.2 | length 73.5
  Layer 6 - Bottom Layer w20: L31.1@2088.43,506.41 L33.2@2161.93,506.41
NetL32_1: L32.1 L36.2 | length 104.2
  Layer 6 - Bottom Layer w10: L32.1@1235.43,494.63 cw(c1237.37,494.63) L32.1@1236,496 ; L32.1@1235.43,505.51 L32.1@1235.43,508.45 ; L36.2@1253.97,439.57 cw(c1253.97,423.97) 1258.14,439 cw(c1253.97,423.97) L36.2@1265,435 ; L36.2@1261,440 L36.2@1268.5,440
  Layer 6 - Bottom Layer w30: L32.1@1235,505 1235.43,505.51 1236.88,507.23 1238.61,509.29 1238.66,508.73 L32.1@1238.66,508.51 ; L32.1@1235.43,494.63 1235.43,439.57 L36.2@1253.97,439.57
NetL33_1: L33.1 L37.2 | length 67.9
  Layer 6 - Bottom Layer w10: L33.1@2226.93,504.91 L33.1@2228.43,506.41
  Layer 6 - Bottom Layer w20: L33.1@2229,499 2229,466.5 L37.2@2252.5,443
NetL38_1: L38.1 L40.2 R93.1 | length 143.9
  Layer 6 - Bottom Layer w10: R93.1@2966.93,576.92 2966.93,511.92 L38.1@2971.93,506.92 ; L38.1@2970.24,466.92 L38.1@2970.24,470.23
  Layer 6 - Bottom Layer w20: L38.1@2971.93,506.92 L40.2@3040.44,506.92
NetL38_2: L38.2 L81.1 R93.2 R154.1 | length 614.5
  Layer 6 - Bottom Layer w10: L38.2@2881.93,491.92 2881.93,341.92 2884.43,339.42 3009.43,339.42 ; L38.2@2883.63,466.92 2883.63,568.61 R93.2@2891.93,576.92 ; L81.1@2986.93,361.92 3009.43,339.42 ; R154.1@3176.93,283.42 3065.44,283.42 3009.43,339.42
NetL39_1: L39.1 L41.2 R124.1 | length 161.2
  Layer 6 - Bottom Layer w10: R124.1@3958.43,581.92 3958.43,545.42 3966.93,536.92 3966.93,501.92 L39.1@3976.93,511.92
  Layer 6 - Bottom Layer w20: L39.1@3976.93,511.92 L41.2@4040.44,511.92
NetL39_2: L39.2 L82.1 R124.2 R155.1 | length 376.7
  Layer 6 - Bottom Layer w10: L82.1@3876.93,356.92 3883.63,363.61 L39.2@3883.63,476.92 ; L39.2@3886.93,476.92 3886.93,573.42 R124.2@3895.44,581.92 ; L82.1@4061.93,356.92 4135.44,283.42 R155.1@4176.93,283.42
NetL40_1: L40.1 L43.2 | length 75.6
  Layer 6 - Bottom Layer w10: L43.2@3171.93,506.92 L43.2@3176.93,511.92
  Layer 6 - Bottom Layer w20: L40.1@3103.43,506.92 L43.2@3171.93,506.92
NetL41_1: L41.1 L44.2 | length 63.5
  Layer 6 - Bottom Layer w20: L41.1@4103.43,511.92 L44.2@4166.93,511.92
NetL43_1: L43.1 L48.2 | length 75.8
  Layer 6 - Bottom Layer w10: L43.1@3236.93,506.92 L43.1@3238.43,505.43 ; L43.1@3238.43,506.92 L43.1@3238.43,505.43 ; L43.1@3240.44,503.42 L43.1@3238.43,505.43
  Layer 6 - Bottom Layer w20: L43.1@3237,501 3237,463.5 L48.2@3259.5,441
NetL44_1: L44.1 L50.2 | length 72.5
  Layer 6 - Bottom Layer w20: L44.1@4237,506 4237,462.5 L50.2@4257.5,442
NetL45_2: L45.2 R174.1 | length 75.7
  Layer 1 - Top Layer w30: L45.2@863.08,5336.92 889.12,5310.88 R174.1@928,5310.88
NetL46_2: L46.2 R175.1 | length 84.7
  Layer 1 - Top Layer w30: L46.2@863.08,5558.08 898.87,5593.87 R175.1@932.92,5593.87
NetL51_1: L51.1 L55.2 R125.1 | length 150.2
  Layer 6 - Bottom Layer w10: L55.2@655.28,6105.02 657.77,6102.52 R125.1@741.28,6102.52 ; L55.2@656.77,6107.02 656.77,6169.52 L51.1@657.28,6170.02
NetL51_2: L51.2 L83.1 R125.2 R185.1 | length 434
  Layer 6 - Bottom Layer w10: L51.2@632.28,6256.02 632.78,6256.52 R185.1@741.28,6256.52 ; R125.2@741.28,6165.52 R185.1@741.28,6256.52 ; R185.1@741.28,6261.02 R185.1@741.28,6256.52 ; R185.1@743.28,6256.52 R185.1@741.28,6256.52 ; R125.2@745.28,6167.02 780.28,6167.02 858.28,6089.02 L83.1@940.28,6089.02
NetL52_2: L52.2 R188.1 | length 113.9
  Layer 1 - Top Layer w30: L52.2@862.99,4163.62 862.99,4132.01 892.87,4102.13 R188.1@932.91,4102.13
NetL53_2: L53.2 R189.1 | length 115.5
  Layer 1 - Top Layer w30: L53.2@862.99,4323.62 862.99,4357.99 890.12,4385.12 R189.1@932.91,4385.12
NetL55_1: L55.1 L57.2 | length 75.5
  Layer 6 - Bottom Layer w10: L57.2@525.28,6124.02 576.78,6124.02 L55.1@593.78,6107.02
NetL57_1: L57.1 L58.2 | length 78.2
  Layer 6 - Bottom Layer w10: L58.2@441.28,6187.02 441.78,6186.52 L57.1@519.28,6186.52
NetL59_2: L59.2 R202.1 | length 115.9
  Layer 1 - Top Layer w30: L59.2@863.08,2922 863.08,2886.92 889.5,2860.5 R202.1@933,2860.5
NetL60_2: L60.2 R203.1 | length 115.9
  Layer 1 - Top Layer w30: L60.2@863.08,3082 863.08,3116.92 889.65,3143.5 R203.1@933,3143.5
NetL62_1: L62.1 L64.2 R126.1 | length 150.1
  Layer 6 - Bottom Layer w10: L64.2@659.5,4864.97 659.5,4930.47 L62.1@660,4930.97 ; L64.2@660,4864.97 664.5,4860.47 R126.1@742,4860.47
NetL62_2: L62.2 L84.1 R126.2 R199.1 | length 345.2
  Layer 6 - Bottom Layer w10: L62.2@632,5016.97 735.5,5016.97 R199.1@742,5010.48 ; R126.2@742,4923.47 742,5008.97 R199.1@745,5011.97 ; R126.2@744,4923.97 791,4923.97 L84.1@858.7,4856.28
NetL64_1: L64.1 L65.2 | length 83.8
  Layer 6 - Bottom Layer w10: L65.2@521,4884.97 569,4884.97 589,4864.97 L64.1@596.5,4864.97
NetL65_1: L65.1 L69.2 | length 81.2
  Layer 6 - Bottom Layer w10: L69.2@440,4944.97 520.5,4944.97 L65.1@521,4945.47
NetL66_2: L66.2 R216.1 | length 117.7
  Layer 1 - Top Layer w30: L66.2@863.08,1680 863.08,1641.92 886.5,1618.5 R216.1@933,1618.5
NetL67_2: L67.2 R217.1 | length 117.7
  Layer 1 - Top Layer w30: L67.2@863.08,1840 863.08,1878.08 886.5,1901.5 R217.1@933,1901.5
NetL70_1: L70.1 L71.2 R127.1 | length 146.2
  Layer 6 - Bottom Layer w10: L71.2@655.5,3623 656,3622.5 L71.2@657.5,3622.5 ; L71.2@656,3621 L71.2@657.5,3622.5 ; L70.1@658.5,3680 658.5,3623.5 L71.2@657.5,3622.5 ; R127.1@741.5,3622.5 L71.2@657.5,3622.5
NetL70_2: L70.2 L85.1 R127.2 R213.1 | length 367.1
  Layer 6 - Bottom Layer w10: L70.2@630.5,3773 631,3772.5 R213.1@741.5,3772.5 R127.2@741.5,3689 ; R127.2@741.5,3685.5 779,3685.5 864.5,3600 L85.1@878.5,3600
NetL71_1: L71.1 L72.2 | length 86.8
  Layer 6 - Bottom Layer w10: L72.2@514.5,3641 516.5,3639 575,3639 L71.1@593,3621
NetL72_1: L72.1 L73.2 | length 59.2
  Layer 6 - Bottom Layer w10: L73.2@452.5,3703.5 511,3703.5 L72.1@511.5,3704
NetL74_1: L74.1 L75.2 R148.1 | length 136
  Layer 6 - Bottom Layer w10: L75.2@653,2376 658.53,2376.04 R148.1@729,2376.5 ; L74.1@658,2441 L75.2@658.5,2381
NetL74_2: L74.2 L86.1 R148.2 R227.1 | length 413.8
  Layer 6 - Bottom Layer w10: R227.1@729,2529.99 729.98,2530 742.42,2530.09 741.53,2451.91 737.09,2447.57 R148.2@736.59,2447.08 ; R148.2@744,2439.5 784.5,2439.5 889,2335 906,2335 ; 906,2337.02 920,2337.02
  Layer 6 - Bottom Layer w20: L74.2@633,2529.31 R227.1@729,2529.99
NetL75_1: L75.1 L76.2 | length 92.5
  Layer 6 - Bottom Layer w10: L76.2@521,2398.5 582,2398.5 L75.1@582,2367
NetL76_1: L76.1 L77.2 | length 76.8
  Layer 6 - Bottom Layer w10: L77.2@441,2460.99 509.78,2460.99 cw(c509.78,2450.78) L76.1@517,2458
NetQ1_1: Q1.1 U7.2 U7.6 | length 679.6
  Layer 1 - Top Layer w10: U7.6@1920.19,6059.09 U7.6@1922.61,6061.51 ; Q1.1@2259.43,6388.21 Q1.1@2259.43,6405.21
  Layer 1 - Top Layer w15: U7.6@1922.61,6061.51 1922.61,6096.53 ; U7.2@1946.93,6224.29 1946.93,6261.13 1971.49,6285.69
  Layer 1 - Top Layer w20: 1922.61,6096.53 2024.1,6198.02 2024.1,6276.71 ; 1971.49,6285.69 2156.91,6285.69 Q1.1@2259.43,6388.21
NetQ2_1: Q2.1 R89.1 U9.20 | length 738.2
  Layer 1 - Top Layer w10: U9.20@6149.49,4940.16 6213.11,4940.16 6253.19,4980.23 v4@6297.54,4980.23
  Layer 6 - Bottom Layer w10: v4@6299.25,4980.8 6299.25,4767.56 6438.49,4628.31 6543.31,4627.11 R89.1@6543.31,4685.66
  other v4: 6299.25,4981.37
NetQ2_3: Q2.3 R102.1 | length 734.9
  Layer 1 - Top Layer w10: v4@6382.84,4094.28 6387.82,4099.26 R102.1@6441.69,4099.26
  Layer 6 - Bottom Layer w10: v4@6383.41,4098.83 6515.33,4098.83 6542.63,4126.12 6542.63,4335.95 6449.31,4429.27 Q2.3@6449.31,4590.91
  other v4: 6383.41,4097.12
NetQ3_4: Q3.4 U8.19 | length 1323.3
  Layer 1 - Top Layer w10: Q3.4@4188.98,4413.39 v2(4228.39,4413.39)
  Layer 4 - Signal w20: v2(3489.41,4975.29) 3539.12,5025 3985,5025 4130,4880 4130,4511.77 v2(4228.39,4413.39)
  Layer 6 - Bottom Layer w15: U8.19@3489.41,4920 v2(3489.41,4975.29)
NetQ4_1: Q4.1 U8.2 | length 1609.2
  Layer 1 - Top Layer w30: v2(4725,4149) Q4.1@4823,4149
  Layer 4 - Signal w30: v2(3489.41,4631.42) 3512.98,4655 3850,4655 4356,4149 v2(4725,4149)
  Layer 6 - Bottom Layer w10: v2(3489.41,4631.42) U8.2@3489.41,4687.72
NetQ4_2: Q4.2 R74.2 Rsense1.2 | length 2273.4
  Layer 1 - Top Layer w10: Rsense1.2@5100,4284.49 v2(5204.49,4284.49)
  Layer 4 - Signal w20: v4(3470,4300) 3510,4300 3580,4230 4050,4230 4295,3985 4775,3985 5074.49,4284.49 v2(5204.49,4284.49)
  Layer 6 - Bottom Layer w20: v4(3470,4300) 3548.84,4378.84 R74.2@3548.84,4447.24
  other v3: 5110,3915 5215,3915 5320,3915 5110,4005 5215,4005 5320,4005 5110,4095 5215,4095 5320,4095 5110,4185 5215,4185 5320,4185
NetQ5_4: Q5.4 U8.16 | length 1551.5
  Layer 1 - Top Layer w10: Q5.4@4326.61,4460.04 v2(4326.61,4498.39)
  Layer 4 - Signal w20: v2(3412.64,4974.65) 3412.64,5012.64 3470,5070 4175,5070 4326.61,4918.39 v2(4326.61,4498.39)
  Layer 6 - Bottom Layer w10: U8.16@3412.64,4920 v2(3412.64,4974.65)
NetQ6_4: Q6.4 Q7.4 R108.2 R109.2 | length 1278.1
  Layer 1 - Top Layer w10: R109.2@3576.38,6008.94 3601.38,6008.94 ; v2(3601.38,6041.38) 3601.38,6008.94 ; R108.2@3626.38,6008.94 3601.38,6008.94
  Layer 1 - Top Layer w20: v2(4265,6190) Q6.4@4265,6237.72 ; v2(4640,6190) Q7.4@4640,6237.72
  Layer 4 - Signal w20: v2(3601.38,6041.38) 3750,6190 v2(4265,6190) v2(4640,6190)
NetQ8_4: Q8.4 Q9.4 R114.2 R115.2 | length 952.6
  Layer 1 - Top Layer w20: 3753.94,5707.68 3947.32,5707.68 v2(3950,5705) ; v2(3950,5255) Q9.4@4032.72,5255 ; v2(3950,5795) Q8.4@4032.72,5795
  Layer 1 - Top Layer w30: R114.2@3753.94,5682.68 3753.94,5707.68 R115.2@3753.94,5732.68
  Layer 4 - Signal w20: v2(3950,5255) v2(3950,5705) v2(3950,5795)
NetR23_1: R23.1 S4.8 | length 94.2
  Layer 1 - Top Layer w10: R23.1@1366,1270.24 1366,1178.29 S4.8@1367.56,1176.74
NetR24_1: R24.1 S4.7 | length 94.2
  Layer 1 - Top Layer w10: R24.1@1416,1270.24 1416,1178.29 S4.7@1417.56,1176.74
NetR27_1: R27.1 S4.6 | length 93.6
  Layer 1 - Top Layer w10: R27.1@1467.42,1270.24 1467.56,1270.11 S4.6@1467.56,1176.74
NetR28_1: R28.1 S4.5 | length 93.7
  Layer 1 - Top Layer w10: S4.5@1517.56,1176.74 1517.56,1269.8 R28.1@1518,1270.24
NetR30_2: R30.2 U1.4 | length 822.1
  Layer 1 - Top Layer w5: v4@2982.7,1524.72 U1.4@3013.35,1524.72 ; v4(3732.56,1530.87) v4@3732.87,1530.55
  Layer 1 - Top Layer w20: R30.2@3732.87,1497.08 v4@3732.87,1530.55
  Layer 4 - Signal w5: v4(2981.56,1525.87) 2988.91,1533.22 3080.2,1533.22 3087.56,1525.87 3727.56,1525.87 v4@3731.41,1529.72
NetR31_1: R31.1 Y1.1 | length 116.4
  Layer 6 - Bottom Layer w10: Y1.1@2164.1,1925.4 2245.79,1925.4 R31.1@2270.31,1949.92
NetR32_1: R32.1 R33.1 R251.1 R252.2
NetR36_1: R36.1 S5.8 | length 91.4
  Layer 1 - Top Layer w10: S5.8@2436.31,5424.2 R36.1@2527.69,5424.2
NetR37_1: R37.1 S5.7 | length 91.4
  Layer 1 - Top Layer w10: S5.7@2436.31,5374.2 R37.1@2527.69,5374.2
NetR40_1: R40.1 S5.6 | length 91.4
  Layer 1 - Top Layer w10: S5.6@2436.31,5324.2 R40.1@2527.69,5324.2
NetR41_1: R41.1 S5.5 | length 91.4
  Layer 1 - Top Layer w10: S5.5@2436.31,5274.2 R41.1@2527.69,5274.2
NetR43_2: R43.2 U2.4 | length 871.4
  Layer 1 - Top Layer w5: U2.4@2275.42,3875.77 2275.42,3898.42 v4(2282,3905)
  Layer 1 - Top Layer w10: R43.2@2190,3103.62 2190,3300 2280,3390 v4(2280,3425)
  Layer 4 - Signal w5: v4(2280,3425) 2282,3427 v4(2282,3905)
NetR44_1: R44.1 R49.1 R50.1 R65.2 R228.1 TP5.1 U4.9 | length 2430.6
  Layer 1 - Top Layer w5: U4.9@6027.56,2702.38 6055.98,2730.81 R65.2@6055.98,2770.06
  Layer 1 - Top Layer w10: R228.1@4951.62,3399.49 5160.86,3399.49 R44.1@5166.38,3405 5175,3413.62 5175,3506.38 ; R50.1@5180.31,3540 5175,3534.69 5175,3506.38 ; v2(5210,3506.38) 5175,3506.38 ; R65.2@6055.98,2777.93 6139.2,2777.93 6156.45,2795.18 TP5.1@6238.02,2795.18
  Layer 4 - Signal w10: v2(5210,3506.38) 5341.65,3506.38 5420.27,3585 5685,3585 5745,3525 5745,3485 5685,3425 5650,3425 5620,3395 5620,3300 5870,3050 5870,2960 5935,2895 6140.86,2895 TP5.1@6238.5,2797.36
NetR63_2: R63.2 U3.12 | length 150.2
  Layer 1 - Top Layer w10: R63.2@5739.84,3375 5751.02,3363.82 U3.12@5885.39,3363.82
NetR64_2: R64.2 U3.13 | length 151
  Layer 1 - Top Layer w10: R64.2@5739.84,3325 5753.07,3338.23 U3.13@5885.39,3338.23
NetR76_1: R76.1 R79.2 U8.6 | length 257.7
  Layer 6 - Bottom Layer w10: R79.2@3248.84,4519.48 3303.84,4519.48 3303.84,4545.86 3387.05,4629.06 U8.6@3387.05,4687.72
NetR78_1: R78.1 R83.2 U8.13 | length 315.9
  Layer 6 - Bottom Layer w10: R78.1@3162.46,5041.69 3162.46,5007.24 3188.84,4980.86 3303.84,4980.86 3335.87,4948.83 U8.13@3335.87,4920
  Layer 6 - Bottom Layer w25: R78.1@3163.84,5043.06 R83.2@3163.84,5098.06
NetR78_2: R78.2 R81.2 U8.12 | length 346.4
  Layer 6 - Bottom Layer w10: R78.2@3108.84,5048.06 R78.2@3115.22,5041.69 3115.22,4994.48 3143.84,4965.86 3288.84,4965.86 3310.28,4944.42 U8.12@3310.28,4920
  Layer 6 - Bottom Layer w25: R78.2@3108.84,5048.06 R81.2@3108.84,5098.06
NetR80_2: R80.2 U8.8 | length 323.1
  Layer 6 - Bottom Layer w10: R80.2@3138.84,4519.48 3138.84,4555.86 3193.84,4610.86 3318.84,4610.86 3335.87,4627.88 U8.8@3335.87,4687.72
NetR85_1: R85.1 R87.2 U9.22 | length 933.3
  Layer 1 - Top Layer w10: U9.22@6149.49,4979.53 6184.53,4979.53 6245,5040 6480,5040 6530,5090 6530,5340 6580,5390 6580,5463.62 R87.2@6545,5498.62 6528.62,5515 R85.1@6528.62,5555
NetR90_2: R90.2 U9.3 | length 103.3
  Layer 1 - Top Layer w10: R90.2@5863.62,4995 5905,4995 5920.47,4979.53 U9.3@5960.51,4979.53
NetR91_1: R91.1 R95.2 U9.6 | length 925.7
  Layer 1 - Top Layer w10: R91.1@5586.38,4355 5570,4371.38 R95.2@5570,4411.38 5540,4441.38 5540,4505 5585,4550 5585,4795 5735,4945 5875,4945 5899.53,4920.47 U9.6@5960.51,4920.47
NetR97_1: R97.1 R101.2 U9.19 | length 975.4
  Layer 1 - Top Layer w10: U9.19@6149.49,4920.47 6215.32,4920.47 6244.85,4950 6400,4950 6410,4940 6410,4815 6435,4790 6475,4790 6570,4695 6570,4425 6556.38,4411.38 R101.2@6545,4411.38 6545,4371.38 R97.1@6528.62,4355
NetR99_2: R99.2 U9.2 | length 129.6
  Layer 1 - Top Layer w10: R99.2@5863.62,5050 5900,5050 5915,5035 5915,5015 5930.79,4999.21 U9.2@5960.51,4999.21
NetR100_2: R100.2 U9.21 | length 398.4
  Layer 1 - Top Layer w10: U9.21@6149.49,4959.84 6199.84,4959.84 6260,5020 6405,5020 6445,4980 R100.2@6445,4918.62
NetR107_2: R107.2 TP10.1 | length 554.3
  Layer 1 - Top Layer w30: v4(3490.95,5530.95) R107.2@3490.95,5577.76
  Layer 6 - Bottom Layer w10: TP10.1@3015.75,5507 3090.76,5507 3117.76,5480 3440,5480 v4(3490.95,5530.95)
NetR136_1: R136.1 R140.2 U11.14 | length 160.1
  Layer 1 - Top Layer w10: U11.14@917.71,970.98 917.71,1001.02 934.56,1017.87 ; 956.18,1097.83 R140.2@956.18,1110.87
  Layer 1 - Top Layer w20: R136.1@934.37,1056.68 938.93,1061.24 R136.1@941.78,1064.09
  Layer 1 - Top Layer w30: 938.56,1017.87 R136.1@938.56,1056.49 ; R136.1@938.93,1060.87 938.93,1061.24 938.93,1080.59 956.18,1097.83
NetR137_1: R137.1 R141.2 U12.14 | length 142.4
  Layer 1 - Top Layer w10: U12.14@1912.72,965.99 1912.72,998.02 1923.94,1009.24
  Layer 1 - Top Layer w20: 1926.56,1071.87 R141.2@1953.8,1099.11
  Layer 1 - Top Layer w30: 1923.56,1010.87 R137.1@1923.56,1066.87
NetR138_1: R138.1 TP18.1 U11.20 | length 421.4
  Layer 1 - Top Layer w5: 837.56,810.87 843.56,810.87
  Layer 1 - Top Layer w10: 837.56,810.87 817.56,830.87 817.56,875.87 828.03,886.34 U11.20@852.75,886.34
  Layer 1 - Top Layer w30: TP18.1@717.56,590.87 825.56,698.87 825.56,792.87 843.56,810.87 R138.1@873.93,810.87
NetR139_1: R139.1 TP19.1 U12.20 | length 444.3
  Layer 1 - Top Layer w10: 1825.56,810.87 1793.56,842.87 1793.56,869.87 1805.03,881.34 U12.20@1847.75,881.34
  Layer 1 - Top Layer w30: TP19.1@1717.56,590.87 1825.56,698.87 1825.56,810.87 R139.1@1873.94,810.87
NetR140_1: R140.1 R142.2 U11.15 | length 194.4
  Layer 1 - Top Layer w10: U11.15@898.03,970.98 898.03,1099.96 R140.1@908.93,1110.87 R142.2@908.94,1160.87
NetR141_1: R141.1 R143.2 U12.15 | length 194.4
  Layer 1 - Top Layer w10: U12.15@1893.03,965.99 1893.03,1094.96 R141.1@1903.94,1105.87 R143.2@1903.94,1155.87
NetR144_2: R144.2 U11.17 | length 52.2
  Layer 1 - Top Layer w10: R144.2@807.56,962.24 824.41,945.39 U11.17@852.75,945.39
NetR145_2: R145.2 U12.17 | length 33.3
  Layer 1 - Top Layer w10: 1814.41,940.39 U12.17@1847.75,940.39
NetR146_2: R146.2 TP20.1 U11.19 | length 325.4
  Layer 1 - Top Layer w5: R146.2@707.56,917.24 R146.2@718.78,906.02
  Layer 1 - Top Layer w10: R146.2@707.56,917.24 707.56,880.87 717.56,870.87 TP20.1@717.56,745.87 ; R146.2@718.78,906.02 U11.19@852.75,906.02
NetR147_2: R147.2 TP21.1 U12.19 | length 306.6
  Layer 1 - Top Layer w10: R147.2@1702.56,912.24 1702.56,760.87 TP21.1@1717.56,745.87 ; R147.2@1713.78,901.03 U12.19@1847.75,901.03
NetR149_1: R149.1 U27.3 | length 87.9
  Layer 1 - Top Layer w15: R149.1@5599.62,2252 U27.3@5687.5,2252
NetR150_1: R150.1 U27.2 | length 92.9
  Layer 1 - Top Layer w15: R150.1@5594.62,2302 U27.2@5687.5,2302
NetR151_1: R151.1 U27.1 | length 99.3
  Layer 1 - Top Layer w15: R151.1@5593.62,2359 5621,2359 5628,2352 U27.1@5689.99,2352
NetR156_1: R156.1 R160.2 U13.14 | length 147.5
  Layer 1 - Top Layer w10: U13.14@2897.72,980.98 2897.72,1059.65 R156.1@2908.94,1070.87
  Layer 1 - Top Layer w30: R160.2@2856.56,1074.87 R156.1@2909.56,1074.87
NetR157_1: R157.1 R161.2 U14.14 | length 139.9
  Layer 1 - Top Layer w10: U14.14@3907.72,965.98 R157.1@3907.72,1044.65 ; R157.1@3918.94,1055.87 3946.18,1083.11 R161.2@3946.18,1105.87
NetR158_1: R158.1 TP24.1 U13.20 | length 443.9
  Layer 1 - Top Layer w10: U13.20@2832.75,896.34 2808.03,896.34 2797.56,885.87 2797.56,840.87 2850.31,788.11
  Layer 1 - Top Layer w30: TP24.1@2717.56,590.87 2819.56,692.87 2819.56,756.49 R158.1@2873.94,810.87
NetR159_1: R159.1 TP25.1 U14.20 | length 426
  Layer 1 - Top Layer w10: U14.20@3842.75,881.34 3823.03,881.34 3812.56,870.87 3812.56,835.87 3837.56,810.87 R159.1@3873.94,810.87
  Layer 1 - Top Layer w30: TP25.1@3717.56,590.87 3872.2,745.51 3872.2,809.14 R159.1@3873.94,810.87
NetR160_1: R160.1 R162.2 U13.15 | length 164.4
  Layer 1 - Top Layer w10: R162.2@2827.56,1124.49 2827.56,1052.24 R160.1@2852.56,1027.24 2878.03,1001.77 U13.15@2878.03,980.98
NetR161_1: R161.1 R163.2 U14.15 | length 179
  Layer 1 - Top Layer w10: U14.15@3888.03,965.98 R161.1@3888.03,1094.96 ; R161.1@3898.94,1105.87 R163.2@3898.94,1155.87
NetR164_2: R164.2 U13.17 | length 28.3
  Layer 1 - Top Layer w10: 2804.41,955.39 U13.17@2832.75,955.39
NetR165_2: R165.2 U14.17 | length 28.3
  Layer 1 - Top Layer w10: 3814.41,940.39 U14.17@3842.75,940.39
NetR166_2: R166.2 TP26.1 U13.19 | length 320.7
  Layer 1 - Top Layer w10: R166.2@2692.56,927.24 2692.56,770.87 TP26.1@2717.56,745.87 ; R166.2@2703.78,916.02 U13.19@2832.75,916.02
NetR167_2: R167.2 TP27.1 U14.19 | length 301.6
  Layer 1 - Top Layer w10: R167.2@3702.56,912.24 3702.56,760.87 TP27.1@3717.56,745.87 ; R167.2@3713.78,901.02 U14.19@3842.75,901.02
NetR176_1: R176.1 R178.2 U15.14 | length 170.8
  Layer 1 - Top Layer w12: U15.14@1610.12,5651.84 1698.78,5651.84 R176.1@1710,5640.62 1737.25,5613.38 R178.2@1765,5613.38
NetR177_1: R177.1 TP29.1 U15.20 | length 365
  Layer 1 - Top Layer w10: 1525,5746 1525.47,5745.53 U15.20@1525.47,5716.8
  Layer 1 - Top Layer w20: R177.1@1455,5665.62 1385,5735.62 TP29.1@1385,5807 1464,5807 1525,5746
NetR178_1: R178.1 R179.2 U15.15 | length 199
  Layer 1 - Top Layer w6: U15.15@1610.12,5671.53 R178.1@1754.1,5671.53 ; R178.1@1765,5660.62 R179.2@1820,5660.62
NetR180_2: R180.2 U15.17 | length 40.7
  Layer 1 - Top Layer w6: U15.17@1584.53,5716.8 R180.2@1584.53,5757.47
NetR181_2: R181.2 TP30.1 U15.19 | length 528
  Layer 1 - Top Layer w5.9: TP30.1@1555,6027 1490,6027 1424,5961 1424,5883 1460,5847 1529,5847 1539,5857 1545.16,5857 R181.2@1556.38,5857
  Layer 1 - Top Layer w6: U15.19@1545.16,5716.8 R181.2@1545.16,5857
NetR190_1: R190.1 R192.2 U17.14 | length 170.8
  Layer 1 - Top Layer w6: U17.14@1610.12,4409.84 1698.78,4409.84 R190.1@1710,4398.62 1721.38,4398.62 1748.62,4371.38 R192.2@1765,4371.38
NetR191_1: R191.1 TP32.1 U17.20 | length 369.7
  Layer 1 - Top Layer w10: 1525,4512 1525,4475.28 U17.20@1525.47,4474.8
  Layer 1 - Top Layer w20: R191.1@1455,4423.62 1385,4493.62 TP32.1@1385,4565 1472,4565 1525,4512
NetR192_1: R192.1 R193.2 U17.15 | length 194
  Layer 1 - Top Layer w6: U17.15@1610.12,4429.53 R192.1@1754.09,4429.53 ; R192.1@1765,4418.62 R193.2@1815,4418.62
NetR194_2: R194.2 U17.17 | length 33.3
  Layer 1 - Top Layer w6: U17.17@1584.53,4474.8 1584.53,4508.15
NetR197_2: R197.2 TP33.1 U17.19 | length 362.6
  Layer 1 - Top Layer w6: U17.19@1545.16,4474.8 R197.2@1545.16,4608.78
  Layer 1 - Top Layer w15: v2(1511,4620) R197.2@1556.38,4620
  Layer 6 - Bottom Layer w10: v2(1511,4620) 1555,4664 TP33.1@1555,4785
NetR204_1: R204.1 R206.2 U19.14 | length 154.9
  Layer 1 - Top Layer w10: U19.14@1610.12,3167.84 R204.1@1698.78,3167.84 ; R204.1@1710,3156.62 1737.24,3129.38 R206.2@1765,3129.38
NetR205_1: R205.1 TP35.1 U19.20 | length 369.1
  Layer 1 - Top Layer w10: 1524,3270 1525.47,3268.53 U19.20@1525.47,3232.8
  Layer 1 - Top Layer w20: R205.1@1455,3181.62 1385,3251.62 TP35.1@1385,3323 1471,3323 1524,3270
NetR206_1: R206.1 R207.2 U19.15 | length 199
  Layer 1 - Top Layer w10: U19.15@1610.12,3187.53 R206.1@1754.09,3187.53 ; R206.1@1765,3176.62 R207.2@1820,3176.62
NetR208_2: R208.2 U19.17 | length 43.2
  Layer 1 - Top Layer w10: U19.17@1584.53,3232.8 R208.2@1584.53,3275.99
NetR209_2: R209.2 TP36.1 U19.19 | length 311.4
  Layer 1 - Top Layer w10: U19.19@1545.16,3232.8 R209.2@1545.16,3378.59 ; TP36.1@1555,3543 1556.38,3541.62 R209.2@1556.38,3378
NetR218_1: R218.1 R220.2 U21.14 | length 154.9
  Layer 1 - Top Layer w10: U21.14@1610.12,1925.84 R218.1@1698.78,1925.84 ; R218.1@1710,1914.62 1737.76,1914.62 R220.2@1765,1887.38
NetR219_1: R219.1 TP38.1 U21.20 | length 381.5
  Layer 1 - Top Layer w10: U21.20@1526,1991.33 1526,2033
  Layer 1 - Top Layer w20: R219.1@1455,1939.62 1440.38,1939.62 1385,1995 TP38.1@1385,2081 1478,2081 1526,2033
NetR220_1: R220.1 R221.2 U21.15 | length 214.4
  Layer 1 - Top Layer w10: U21.15@1610.12,1945.53 1754.09,1945.53 R220.1@1765,1934.62 R221.2@1820,1934.62
NetR222_2: R222.2 U21.17 | length 33.3
  Layer 1 - Top Layer w10: U21.17@1584.53,1990.8 1584.53,2024.15
NetR225_2: R225.2 TP39.1 U21.19 | length 299.5
  Layer 1 - Top Layer w10: U21.19@1545.16,1990.8 R225.2@1545.16,2124.78 ; TP39.1@1555,2301 1556.38,2299.62 R225.2@1556.38,2136
NetR229_1: R229.1 R231.2 U23.1 | length 90.2
  Layer 6 - Bottom Layer w30: R231.2@700.56,5990.15 R229.1@700.56,6040.15 ; U23.1@707.53,5942.96 R231.2@707.53,5983.18
NetR232_2: R232.2 U23.6 | length 76.3
  Layer 6 - Bottom Layer w10: R232.2@742.96,5762.29 U23.6@742.96,5838.63
NetR234_1: R234.1 R236.2 U24.1 | length 98.1
  Layer 6 - Bottom Layer w10: R234.1@701.18,4796.06 R236.2@701.18,4746.06 708.47,4738.78 U24.1@708.47,4701.02
NetR235_1: R235.1 S3.8 | length 73.5
  Layer 1 - Top Layer w10: S3.8@5049.14,3220 R235.1@5122.67,3220
NetR237_2: R237.2 U24.6 | length 84.2
  Layer 6 - Bottom Layer w10: R237.2@746.38,4510 U24.6@746.38,4594.21
NetR238_1: R238.1 S3.7 | length 74.5
  Layer 1 - Top Layer w10: S3.7@5049.14,3170 R238.1@5123.61,3170
NetR239_1: R239.1 R241.2 U25.1 | length 89.1
  Layer 6 - Bottom Layer w5.9: U25.1@708.53,3458.96 R239.1@708.53,3548.09
NetR240_1: R240.1 S3.6 | length 75.3
  Layer 1 - Top Layer w10: S3.6@5049.14,3120 5123.02,3120 R240.1@5124.05,3118.97
NetR242_2: R242.2 U25.6 | length 87.5
  Layer 6 - Bottom Layer w10: R242.2@715.38,3279 743.96,3307.58 U25.6@743.96,3354.63
NetR243_1: R243.1 S3.5 | length 74.9
  Layer 1 - Top Layer w10: S3.5@5049.14,3070 R243.1@5124.05,3070
NetR244_1: R244.1 R246.2 U26.1 | length 89.1
  Layer 6 - Bottom Layer w10: R246.2@702.62,2262 R244.1@702.62,2312 ; U26.1@708.53,2216.96 R246.2@708.53,2256.09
